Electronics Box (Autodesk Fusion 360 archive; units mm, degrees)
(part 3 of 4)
sketch "Sketch39" plane through (-44.05, 0, 0) normal (-1, 0, 0) x axis (0, -1, 0)
  line L1 (119.3333, 23.3545) -> (140.5403, 36.2986)
  line L2 (116.9188, 37.6536) -> (116.9188, 24.7095)
  line L3 (139.7132, 39.2411) -> (118.5063, 39.2411)
  line L4 (133.8107, 47.0651) -> (122.3147, 51.6626)
  line L5 (116.125, 44.0036) -> (133.2212, 44.0036)
  line L6 (114.5375, 47.3251) -> (114.5375, 45.5911)
  line L7 (153.8331, 21.6063) -> (153.8331, 36.0038)
  line L8 (128.6574, 20.0188) -> (152.2456, 20.0188)
  line L9 (151.4185, 37.3588) -> (127.8303, 22.9613)
  line L10 (87.9482, 38.7249) -> (109.672, 23.8539)
  line L11 (110.5688, 41.6224) -> (88.845, 41.6224)
  line L12 (112.1563, 25.1639) -> (112.1563, 40.0349)
  line L13 (136.171, 12.1797) -> (145.909, 8.5803)
  line L14 (152.2456, 15.2563) -> (136.7214, 15.2563)
  line L15 (153.8331, 13.1249) -> (153.8331, 13.6688)
  line L16 (106.0893, 20.535) -> (84.3655, 35.406)
  line L17 (83.4688, 17.6375) -> (105.1925, 17.6375)
  line L18 (81.8812, 34.096) -> (81.8813, 19.225)
  line L19 (143.8207, 57.3375) -> (129.195, 57.3375)
  line L20 (153.8331, 46.5316) -> (153.8331, 47.3251)
  line L21 (128.6056, 54.276) -> (151.6561, 45.0576)
  line L22 (124.5499, 3.1125) -> (138.0913, 3.1125)
  line L23 (138.6417, 6.189) -> (116.6477, 14.3188)
  line L24 (20.9087, 3.1125) -> (34.4501, 3.1125)
  line L25 (42.3523, 14.3188) -> (20.3583, 6.189)
  line L26 (29.805, 57.3375) -> (15.1793, 57.3375)
  line L27 (7.3439, 45.0576) -> (30.3944, 54.276)
  line L28 (5.1669, 47.3251) -> (5.1669, 46.5316)
  line L29 (74.6345, 35.406) -> (52.9107, 20.535)
  line L30 (77.1188, 19.225) -> (77.1188, 34.096)
  line L31 (53.8075, 17.6375) -> (75.5312, 17.6375)
  line L32 (34.5367, -1.65) -> (15.0927, -1.65)
  line L33 (104.6117, -1.65) -> (54.3883, -1.65)
  line L34 (143.9073, -1.65) -> (124.4633, -1.65)
  line L35 (158.5956, 47.4117) -> (158.5956, 13.0383)
  line L36 (124.4633, 62.1) -> (143.9073, 62.1)
  line L37 (54.3883, 62.1) -> (104.6117, 62.1)
  line L38 (15.0927, 62.1) -> (34.5367, 62.1)
  line L39 (0.4044, 13.0383) -> (0.4044, 47.4117)
  line L40 (5.1669, 13.6688) -> (5.1669, 13.1249)
  line L41 (22.2786, 15.2563) -> (6.7544, 15.2563)
  line L42 (13.091, 8.5803) -> (22.829, 12.1797)
  line L43 (46.8437, 40.0349) -> (46.8437, 25.1639)
  line L44 (70.155, 41.6224) -> (48.4312, 41.6224)
  line L45 (49.328, 23.8539) -> (71.0518, 38.7249)
  line L46 (5.1669, 36.0038) -> (5.1669, 21.6063)
  line L47 (31.1697, 22.9613) -> (7.5815, 37.3588)
  line L48 (6.7544, 20.0188) -> (30.3426, 20.0188)
  line L49 (44.4625, 45.5911) -> (44.4625, 47.3251)
  line L50 (25.7788, 44.0036) -> (42.875, 44.0036)
  line L51 (36.6853, 51.6626) -> (25.1893, 47.0651)
  line L52 (18.4597, 36.2986) -> (39.6667, 23.3545)
  line L53 (40.4937, 39.2411) -> (19.2868, 39.2411)
  line L54 (42.0812, 24.7095) -> (42.0812, 37.6536)
  line L55 (136.6611, 46) -> (156.8611, 46)
  line L56 (136.6611, 62.1) -> (136.6611, 46)
  line L57 (156.8611, 46) -> (156.8611, 62.1)
  line L58 (136.6611, 62.1) -> (156.8611, 62.1)
  line L59 (169.3015, 46) -> (136.6611, 46)
  line L60 (169.3015, 68.2941) -> (169.3015, 46)
  line L61 (136.6611, 68.2941) -> (169.3015, 68.2941)
  line L62 (136.6611, 46) -> (136.6611, 68.2941)
  line L63 (153.8331, 3.1125) -> (153.8331, 57.3375)
  circle C1 centre (108.075, 48.0849) radius 1.7
  circle C2 centre (89.025, 48.0849) radius 1.7
  arc A1 centre (118.5063, 24.7095) radius 1.5875 clockwise from (119.3333, 23.3545) to (116.9188, 24.7095)
  arc A2 centre (118.5063, 37.6536) radius 1.5875 clockwise from (116.9188, 37.6536) to (118.5063, 39.2411)
  arc A3 centre (139.7132, 37.6536) radius 1.5875 clockwise from (139.7132, 39.2411) to (140.5403, 36.2986)
  arc A4 centre (114.5375, 57.3375) radius 8.55 clockwise from (120.5996, 51.3081) to (115.8764, 48.893)
  arc A5 centre (121.7252, 50.1886) radius 1.5875 clockwise from (120.5996, 51.3081) to (122.3147, 51.6626)
  arc A6 centre (133.2212, 45.5911) radius 1.5875 clockwise from (133.8107, 47.0651) to (133.2212, 44.0036)
  arc A7 centre (116.125, 45.5911) radius 1.5875 clockwise from (116.125, 44.0036) to (114.5375, 45.5911)
  arc A8 centre (116.125, 47.3251) radius 1.5875 clockwise from (114.5375, 47.3251) to (115.8764, 48.893)
  arc A9 centre (152.2456, 21.6063) radius 1.5875 clockwise from (153.8331, 21.6063) to (152.2456, 20.0188)
  arc A10 centre (128.6574, 21.6063) radius 1.5875 clockwise from (128.6574, 20.0188) to (127.8303, 22.9613)
  arc A11 centre (152.2456, 36.0038) radius 1.5875 clockwise from (151.4185, 37.3588) to (153.8331, 36.0038)
  arc A12 centre (110.5688, 25.1639) radius 1.5875 clockwise from (112.1563, 25.1639) to (109.672, 23.8539)
  arc A13 centre (88.845, 40.0349) radius 1.5875 clockwise from (87.9482, 38.7249) to (88.845, 41.6224)
  arc A14 centre (110.5688, 40.0349) radius 1.5875 clockwise from (110.5688, 41.6224) to (112.1563, 40.0349)
  circle C3 centre (108.075, 11.175) radius 1.7
  circle C4 centre (89.025, 11.175) radius 1.7
  arc A15 centre (153.8331, 3.1125) radius 8.55 clockwise from (147.6141, 8.9799) to (152.4942, 11.557)
  arc A16 centre (146.4594, 10.0693) radius 1.5875 clockwise from (147.6141, 8.9799) to (145.909, 8.5803)
  arc A17 centre (136.7214, 13.6688) radius 1.5875 clockwise from (136.171, 12.1797) to (136.7214, 15.2563)
  arc A18 centre (152.2456, 13.6688) radius 1.5875 clockwise from (152.2456, 15.2563) to (153.8331, 13.6688)
  arc A19 centre (152.2456, 13.1249) radius 1.5875 clockwise from (153.8331, 13.1249) to (152.4942, 11.557)
  arc A20 centre (105.1925, 19.225) radius 1.5875 clockwise from (106.0893, 20.535) to (105.1925, 17.6375)
  arc A21 centre (83.4688, 19.225) radius 1.5875 clockwise from (83.4688, 17.6375) to (81.8813, 19.225)
  arc A22 centre (83.4687, 34.096) radius 1.5875 clockwise from (81.8812, 34.096) to (84.3655, 35.406)
  arc A23 centre (143.8207, 55.75) radius 1.5875 clockwise from (143.8207, 57.3375) to (145.3886, 55.9986)
  arc A24 centre (153.8331, 57.3375) radius 8.55 clockwise from (152.4942, 48.893) to (145.3886, 55.9986)
  arc A25 centre (152.2456, 47.3251) radius 1.5875 clockwise from (152.4942, 48.893) to (153.8331, 47.3251)
  arc A26 centre (152.2456, 46.5316) radius 1.5875 clockwise from (153.8331, 46.5316) to (151.6561, 45.0576)
  arc A27 centre (129.195, 55.75) radius 1.5875 clockwise from (128.6056, 54.276) to (129.195, 57.3375)
  arc A28 centre (124.5499, 4.7) radius 1.5875 clockwise from (124.5499, 3.1125) to (122.982, 4.4514)
  arc A29 centre (114.5375, 3.1125) radius 8.55 clockwise from (115.8764, 11.557) to (122.982, 4.4514)
  arc A30 centre (116.125, 13.1249) radius 1.5875 clockwise from (115.8764, 11.557) to (114.5375, 13.1249)
  arc A31 centre (116.0973, 12.8297) radius 1.5875 clockwise from (114.5375, 13.1249) to (116.6477, 14.3188)
  arc A32 centre (138.0913, 4.7) radius 1.5875 clockwise from (138.6417, 6.189) to (138.0913, 3.1125)
  circle C5 centre (114.5375, 3.1125) radius 2.2
  circle C6 centre (153.8331, 57.3375) radius 2.2
  circle C7 centre (114.5375, 57.3375) radius 2.2
  circle C8 centre (153.8331, 3.1125) radius 2.2
  circle C9 centre (5.1669, 3.1125) radius 2.2
  circle C10 centre (44.4625, 57.3375) radius 2.2
  circle C11 centre (5.1669, 57.3375) radius 2.2
  circle C12 centre (44.4625, 3.1125) radius 2.2
  arc A33 centre (20.9087, 4.7) radius 1.5875 clockwise from (20.9087, 3.1125) to (20.3583, 6.189)
  arc A34 centre (42.9027, 12.8297) radius 1.5875 clockwise from (42.3523, 14.3188) to (44.4625, 13.1249)
  arc A35 centre (42.875, 13.1249) radius 1.5875 clockwise from (44.4625, 13.1249) to (43.1236, 11.557)
  arc A36 centre (44.4625, 3.1125) radius 8.55 clockwise from (36.018, 4.4514) to (43.1236, 11.557)
  arc A37 centre (34.4501, 4.7) radius 1.5875 clockwise from (36.018, 4.4514) to (34.4501, 3.1125)
  arc A38 centre (29.805, 55.75) radius 1.5875 clockwise from (29.805, 57.3375) to (30.3944, 54.276)
  arc A39 centre (6.7544, 46.5316) radius 1.5875 clockwise from (7.3439, 45.0576) to (5.1669, 46.5316)
  arc A40 centre (6.7544, 47.3251) radius 1.5875 clockwise from (5.1669, 47.3251) to (6.5058, 48.893)
  arc A41 centre (5.1669, 57.3375) radius 8.55 clockwise from (13.6114, 55.9986) to (6.5058, 48.893)
  arc A42 centre (15.1793, 55.75) radius 1.5875 clockwise from (13.6114, 55.9986) to (15.1793, 57.3375)
  arc A43 centre (75.5312, 34.096) radius 1.5875 clockwise from (74.6345, 35.406) to (77.1188, 34.096)
  arc A44 centre (75.5312, 19.225) radius 1.5875 clockwise from (77.1188, 19.225) to (75.5312, 17.6375)
  arc A45 centre (53.8075, 19.225) radius 1.5875 clockwise from (53.8075, 17.6375) to (52.9107, 20.535)
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  point P233 (136.6611, 46)
  point P236 (136.6611, 46)
  point P73 (153.8331, 57.3375)
  point P240 (153.8331, 57.3375)
  point P48 (153.8331, 3.1125)
  point P241 (153.8331, 3.1125)
  point P242 (153.8331, 37.45)
  horizontal L59
  vertical L60
  horizontal L61
  vertical L62
  coincident P233 P236
  coincident P73 P240
  coincident P48 P241
  coincident L63 P242
  dimension "d441" diameter = 4.4 (= "threadedinsertdiam")
  dimension "d442" = 6.35
extrude "Extrude16" cut sketch "Sketch39" against normal blind 20.32
delete_face "DeleteFace6"
delete_face "DeleteFace7"
delete_face "DeleteFace8"
delete_face "DeleteFace9"
extrude "Extrude17" add sketch "Sketch39" against normal blind 6.35
delete_face "DeleteFace10"
fillet "Fillet6" radius 1.5875 (= "( 1 / 16 ) * 1 in")
fillet "Fillet7" radius 6.35
hole "Hole2" HoleDepth 10.0076 HoleDiameter 4.4 (= "threadedinsertdiam") TipAngle 180
move_face "MoveFace3"
sketch "Sketch40" plane through (0, 0, 74.8) normal (0, 0, 1) x axis (-1, 0, 0)
  line L1 (-98.3649, 123.85) -> (-98.3649, 92.3)
  line L2 (-75.3149, 123.85) -> (-98.3649, 123.85)
  line L3 (-75.3149, 92.3) -> (-75.3149, 123.85)
  line L4 (-98.3649, 92.3) -> (-75.3149, 92.3)
  line L5 (-118.7303, 25.9568) -> (-118.7303, 131.375)
  line L6 (33.9803, 25.9568) -> (-118.7303, 25.9568)
  line L7 (33.9803, 131.375) -> (33.9803, 25.9568)
  line L8 (-118.7303, 131.375) -> (33.9803, 131.375)
  line L9 (-76.5649, 35.4818) -> (-76.5649, 65.025)
  line L10 (-97.1149, 35.4818) -> (-76.5649, 35.4818)
  line L11 (-97.1149, 65.025) -> (-97.1149, 35.4818)
  line L12 (-76.5649, 65.025) -> (-97.1149, 65.025)
  line L13 (-107.4375, 25.9568) -> (-118.7303, 25.9568)
  line L14 (-118.7303, 131.375) -> (-107.4375, 131.375)
  line L15 (-118.7303, 25.9568) -> (-118.7303, 131.375)
  line L16 (22.6875, 25.9568) -> (33.9803, 25.9568)
  line L17 (22.6875, 131.375) -> (22.6875, 25.9568)
  line L18 (33.9803, 131.375) -> (22.6875, 131.375)
  line L19 (33.9803, 25.9568) -> (33.9803, 131.375)
  line L20 (-70.5524, 131.375) -> (-70.5524, 25.9568)
  line L21 (22.6875, 126.6125) -> (-70.5524, 126.6125)
  line L22 (22.6875, 30.7193) -> (-70.5524, 30.7193)
  line L23 (-47.2424, 126.6125) -> (-47.2424, 30.7193)
  line L24 (-23.9325, 30.7193) -> (-23.9325, 126.6125)
  line L25 (-0.6225, 126.6125) -> (-0.6225, 30.7193)
  line L26 (-70.5524, 54.6926) -> (-47.2424, 30.7193)
  line L27 (-47.2424, 78.6659) -> (-70.5524, 54.6926)
  line L28 (-70.5524, 102.6392) -> (-47.2424, 78.6659)
  line L29 (-47.2424, 126.6125) -> (-70.5524, 102.6392)
  line L30 (-47.2424, 54.6926) -> (-70.5524, 54.6926)
  line L31 (-47.2424, 102.6392) -> (-70.5524, 102.6392)
  line L32 (-70.5524, 78.6659) -> (-47.2424, 78.6659)
  line L33 (-23.9325, 54.6926) -> (-47.2424, 30.7193)
  line L34 (-47.2424, 78.6659) -> (-23.9325, 54.6926)
  line L35 (-47.2424, 54.6926) -> (-23.9325, 54.6926)
  line L36 (-23.9325, 78.6659) -> (-47.2424, 78.6659)
  line L37 (-23.9325, 102.6392) -> (-47.2424, 78.6659)
  line L38 (-23.9325, 102.6392) -> (-47.2424, 126.6125)
  line L39 (-47.2424, 102.6392) -> (-23.9325, 102.6392)
  line L40 (-0.6225, 78.6659) -> (-23.9325, 54.6926)
  line L41 (-0.6225, 54.6926) -> (-23.9325, 54.6926)
  line L42 (-23.9325, 54.6926) -> (-0.6225, 30.7193)
  line L43 (22.6875, 54.6926) -> (-0.6225, 30.7193)
  line L44 (-0.6225, 54.6926) -> (22.6875, 54.6926)
  line L45 (-0.6225, 78.6659) -> (22.6875, 54.6926)
  line L46 (22.6875, 102.6392) -> (-0.6225, 78.6659)
  line L47 (-0.6225, 126.6125) -> (22.6875, 102.6392)
  line L48 (-23.9325, 102.6392) -> (-0.6225, 126.6125)
  line L49 (-23.9325, 102.6392) -> (-0.6225, 78.6659)
  line L50 (-0.6225, 102.6392) -> (22.6875, 102.6392)
  line L51 (-0.6225, 102.6392) -> (-23.9325, 102.6392)
  line L52 (-23.9325, 78.6659) -> (-0.6225, 78.6659)
  line L53 (22.6875, 78.6659) -> (-0.6225, 78.6659)
  circle C1 centre (29.15, 51.2) radius 1.7
  circle C2 centre (29.15, 107.8) radius 1.7
  circle C3 centre (-113.9, 107.8) radius 1.7
  circle C4 centre (-113.9, 51.2) radius 1.7
  point P20 (-107.4375, 131.375)
  point P7 (-118.7303, 25.9568)
  point P18 (-118.7303, 25.9568)
  point P24 (22.6875, 131.375)
  point P8 (33.9803, 25.9568)
  point P22 (33.9803, 25.9568)
  point P26 (-70.5524, 25.9568)
  point P27 (-70.5524, 131.375)
  point P28 (-70.5524, 126.6125)
  point P29 (22.6875, 126.6125)
  point P30 (-70.5524, 30.7193)
  point P31 (22.6875, 30.7193)
  point P32 (-47.2424, 30.7193)
  point P33 (-47.2424, 126.6125)
  point P34 (-23.9325, 126.6125)
  point P35 (-23.9325, 30.7193)
  point P36 (-0.6225, 30.7193)
  point P37 (-0.6225, 126.6125)
  point P38 (-70.5524, 54.6926)
  point P39 (-47.2424, 78.6659)
  point P40 (-70.5524, 102.6392)
  point P41 (-47.2424, 54.6926)
  point P42 (-47.2424, 102.6392)
  point P43 (-70.5524, 78.6659)
  point P44 (-23.9325, 54.6926)
  point P45 (-47.2424, 54.6926)
  point P46 (-23.9325, 78.6659)
  point P47 (-23.9325, 102.6392)
  point P48 (-47.2424, 102.6392)
  point P52 (-0.6225, 30.7193)
  point P56 (-0.6225, 126.6125)
  point P53 (22.6875, 54.6926)
  point P50 (-0.6225, 78.6659)
  point P55 (22.6875, 102.6392)
  point P54 (-0.6225, 54.6926)
  point P58 (-0.6225, 102.6392)
  point P49 (-23.9325, 54.6926)
  point P51 (-0.6225, 54.6926)
  point P57 (-23.9325, 102.6392)
  point P59 (-0.6225, 102.6392)
  point P60 (-0.6225, 78.6659)
  point P61 (-23.9325, 78.6659)
  point P62 (-0.6225, 78.6659)
  point P63 (22.6875, 78.6659)
  point P15 (29.15, 107.8)
  point P5 (-75.3149, 92.3)
  horizontal L13
  horizontal L14
  vertical L15
  coincident L8 P20
  coincident P7 P18
  horizontal L16
  vertical L17
  horizontal L18
  vertical L19
  coincident L8 P24
  coincident P8 P22
  coincident L6 P26
  coincident L8 P27
  perpendicular L8 L20
  coincident L20 P28
  coincident L17 P29
  perpendicular L17 L21
  coincident L20 P30
  coincident L17 P31
  perpendicular L17 L22
  coincident L22 P32
  coincident L21 P33
  perpendicular L21 L23
  coincident L21 P34
  coincident L22 P35
  perpendicular L22 L24
  coincident L22 P36
  coincident L21 P37
  perpendicular L21 L25
  coincident L20 P38
  coincident L23 P39
  coincident L20 P40
  coincident L23 P41
  perpendicular L23 L30
  coincident L23 P42
  perpendicular L23 L31
  coincident L20 P43
  perpendicular L20 L32
  coincident L24 P44
  coincident L23 P45
  perpendicular L23 L35
  midpoint L24 P46
  coincident L24 P47
  coincident L23 P48
  perpendicular L23 L39
  symmetric P32 L24 P52
  symmetric P33 L24 P56
  symmetric L24 P38 P53
  symmetric L24 P39 P50
  symmetric L24 P40 P55
  symmetric L24 P41 P54
  symmetric L24 P42 P58
  symmetric L24 P44 P49
  symmetric L24 P45 P51
  symmetric L24 P47 P57
  symmetric L24 P48 P59
  symmetric L24 P39 P60
  symmetric L24 P46 P61
  symmetric L24 P39 P62
  symmetric L24 P43 P63
  dimension "d455" distance P15 L17 = 6.4625 (= "( ( 3 / 16 ) * 1 in ) + ( m3screwdiam / 2 )")
  dimension "d456" distance P5 L20 = 4.7625 (= "( 3 / 16 ) * 1 in")
  dimension "d457" distance L6 L22 = 4.7625 (= "( 3 / 16 ) * 1 in")
  dimension "d458" distance L8 L21 = 4.7625 (= "( 3 / 16 ) * 1 in")
  dimension "d459" distance L20 L23 = 23.31 (= "3.6708627805633998 in / 4")
  dimension "d460" distance L20 L24 = 46.62 (= "3.6708627805633998 in / 2")
  dimension "d461" distance L20 L25 = 69.9299 (= "3.6708627805633998 in * 0.75")
  dimension "d462" distance P33 P39 = 47.9466 (= "3.7753228345999998 in / 2")
  dimension "d463" distance P30 P38 = 23.9733 (= "3.7753228345999998 in / 4")
  dimension "d464" distance P35 P44 = 23.9733 (= "3.7753228345999998 in / 4")
  dimension "d465" distance P28 P40 = 23.9733 (= "3.7753228345999998 in / 4")
  dimension "d466" distance P34 P47 = 23.9733 (= "3.7753228345999998 in / 4")
hole "Hole1" HoleDepth 10.0076 HoleDiameter 3.4 (= "m3screwdiam") TipAngle 180
extrude "Extrude2" cut sketch "Sketch40" profile of L17 L20 L21 L22 L23 L24 L25 L26 L27 L28 L29 L30 L31 L32 L33 L34 L35 L36 L37 L38 L39 L40 L41 L42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 against normal blind 30.48
web "Web1" Thickness 4.7625 (= "( 3 / 16 ) * 1 in") Depth 6.35
fillet "Fillet1" radius 1.5875 (= "( 1 / 16 ) * 1 in")
hole "Hole2" HoleDepth 10.0076 HoleDiameter 4.4 (= "threadedinsertdiam") TipAngle 180
offset_faces "OffsetFaces1" distance -0.5
offset_faces "OffsetFaces2" distance 0.5
position "Position26"
sketch "Sketch41" plane through (0, 0, 68.45) normal (0, 0, 1) x axis (-1, 0, 0)
  line L1 (-90.9149, 154.35) -> (-90.9149, 141.35)
  line L2 (-88.4149, 157.35) -> (-90.9149, 154.35)
  line L3 (-85.2649, 157.35) -> (-88.4149, 157.35)
  line L4 (-82.7649, 154.35) -> (-85.2649, 157.35)
  line L5 (-82.7649, 141.35) -> (-82.7649, 154.35)
  line L6 (-90.9149, 141.35) -> (-82.7649, 141.35)
  line L7 (-93.1899, 97.475) -> (-80.4899, 97.475)
  line L8 (-93.1899, 118.675) -> (-93.1899, 97.475)
  line L9 (-80.4899, 118.675) -> (-93.1899, 118.675)
  line L10 (-80.4899, 97.475) -> (-80.4899, 118.675)
  line L11 (-116.1, 79.5) -> (-116.1, 158.6)
  line L12 (31.35, 79.5) -> (-116.1, 79.5)
  line L13 (31.35, 158.6) -> (31.35, 79.5)
  line L14 (-84.35, 190.35) -> (-0.4, 190.35)
  circle C1 centre (-113.9, 107.8) radius 1.7
  circle C2 centre (20.495, 179.495) radius 1.7
  circle C3 centre (-105.245, 179.495) radius 1.7
  circle C4 centre (29.15, 107.8) radius 1.7
  arc A1 centre (-0.4, 158.6) radius 31.75 clockwise from (-0.4, 190.35) to (31.35, 158.6)
  arc A2 centre (-84.35, 158.6) radius 31.75 clockwise from (-116.1, 158.6) to (-84.35, 190.35)
  circle C5 centre (-140.4555, 194.1596) radius 1.7
  circle C6 centre (-140.4555, 194.1596) radius 4.875
  dimension "d481" diameter C5 = 3.4 (= "m3screwdiam")
  dimension "d482" = 3.175
extrude "Extrude61" new body sketch "Sketch41" profile of C5 C6 along normal blind 6.35
move "Move2"
align "Align20"
copy_paste_bodies "CopyPasteBodies21"
move "Move23"
copy_paste_bodies "CopyPasteBodies22"
move "Move24"
copy_paste_bodies "CopyPasteBodies23"
move "Move25"
align "Align21"
align "Align22"
align "Align23"
component_from_bodies "Body->Comp9"
copy_paste_bodies "CutPasteBodies1"
copy_paste_bodies "CopyPasteBodies1"
move "Move2"
align "Align1"
copy_paste_bodies "CopyPasteBodies24"
move "Move26"
copy_paste_bodies "CopyPasteBodies25"
move "Move27"
copy_paste_bodies "CopyPasteBodies26"
move "Move28"
copy_paste_bodies "CopyPasteBodies27"
move "Move29"
copy_paste_bodies "CopyPasteBodies28"
move "Move30"
copy_paste_bodies "CopyPasteBodies29"
move "Move31"
copy_paste_bodies "CopyPasteBodies30"
move "Move32"
align "Align24"
align "Align25"
align "Align26"
align "Align27"
align "Align28"
align "Align29"
align "Align30"
mirror "Mirror10" mirrorStitchTolerance 0.1016
align "Align31"
copy_paste_bodies "CopyPasteBodies31"
move "Move33"
align "Align32"
copy_paste_bodies "CutPasteBodies2"
copy_paste "CutPaste8"
copy_paste_bodies "CopyPasteBodies32"
move "Move34"
align "Align33"
copy_paste_bodies "CopyPasteBodies33"
move "Move35"
align "Align34"
copy_paste_bodies "CopyPasteBodies34"
move "Move36"
align "Align35"
copy_paste_bodies "CopyPasteBodies35"
move "Move37"
align "Align36"
copy_paste_bodies "CutPasteBodies3"
copy_paste_bodies "CutPasteBodies5"
as_built_joint "As-built2"
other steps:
base_feature "Base Feature1"
base_feature "Base Feature1"
base_feature "Base Feature1"
base_feature "Base Feature1"
base_feature "Base Feature1"
base_feature "Base Feature1"
base_feature "Base Feature1"
base_feature "Base Feature1"
base_feature "Base Feature1"
base_feature "Base Feature1"
base_feature "Base Feature1"
base_feature "Base Feature2"
base_feature "Base Feature2"
base_feature "Base Feature2"
base_feature "Base Feature2"
base_feature "Base Feature2"
base_feature "Base Feature2"
base_feature "Base Feature2"
base_feature "Base Feature2"
base_feature "Base Feature2"
base_feature "Base Feature2"
base_feature "Base Feature3"
base_feature "Base Feature1"
base_feature "Base Feature4"
base_feature "Base Feature5"
base_feature "Base Feature2"
base_feature "Base Feature1"
delete_face "DeleteFace2"
delete_face "DeleteFace3"
delete_face "DeleteFace4"
base_feature "Base Feature6"
base_feature "Base Feature1"
base_feature "Base Feature2"
base_feature "Base Feature3"
base_feature "Base Feature3"
base_feature "Base Feature4"
base_feature "Base Feature1"
base_feature "Base Feature2"
base_feature "Base Feature3"
base_feature "Base Feature4"
base_feature "Base Feature5"
base_feature "Base Feature6"
base_feature "Base Feature7"
base_feature "Base Feature8"
base_feature "Base Feature9"
base_feature "Base Feature10"
base_feature "Base Feature11"
base_feature "Base Feature12"
base_feature "Base Feature13"
base_feature "Base Feature14"
base_feature "Base Feature15"
base_feature "Base Feature16"
base_feature "Base Feature17"
base_feature "Base Feature18"
base_feature "Base Feature19"
base_feature "Base Feature20"
base_feature "Base Feature21"
base_feature "Base Feature22"
base_feature "Base Feature23"
base_feature "Base Feature24"
base_feature "Base Feature25"
base_feature "Base Feature26"
base_feature "Base Feature27"
base_feature "Base Feature28"
base_feature "Base Feature29"
base_feature "Base Feature30"
base_feature "Base Feature31"
base_feature "Base Feature32"
base_feature "Base Feature33"
base_feature "Base Feature34"
base_feature "Base Feature35"
create_component "CreateComponent1"
remove_instance "RemoveInstance1"
remove_instance "RemoveInstance2"
remove_instance "RemoveInstance3"
remove_instance "RemoveInstance4"
remove_instance "RemoveInstance5"
remove_instance "RemoveInstance6"
remove_instance "RemoveInstance7"
remove_instance "RemoveInstance8"
create_component "CreateComponent2"
remove_instance "RemoveInstance9"
remove_instance "RemoveInstance10"
remove_instance "RemoveInstance11"
create_component "CreateComponent3"
remove_instance "RemoveInstance12"
remove_instance "RemoveInstance13"
remove_instance "RemoveInstance14"
remove_instance "RemoveInstance15"
create_component "CreateComponent4"
remove_body "RemoveBody3"
remove_body "RemoveBody4"
create_component "CreateComponent5"
remove_body "RemoveBody5"
create_component "CreateComponent6"
remove_body "RemoveBody6"
remove_body "RemoveBody7"
remove_body "RemoveBody8"
create_component "CreateComponent7"
remove_body "RemoveBody9"
remove_body "RemoveBody10"
create_component "CreateComponent8"
create_component "CreateComponent9"
remove_instance "RemoveInstance16"
remove_instance "RemoveInstance17"
remove_instance "RemoveInstance18"
remove_instance "RemoveInstance19"
remove_instance "RemoveInstance20"
create_component "CreateComponent10"
create_component "CreateComponent1"
remove_body "RemoveBody1"
create_component "CreateComponent2"
remove_body "RemoveBody2"
remove_body "RemoveBody11"
remove_body "RemoveBody12"
remove_body "RemoveBody13"
remove_body "RemoveBody14"
remove_body "RemoveBody15"
remove_body "RemoveBody16"
remove_body "RemoveBody17"
remove_body "RemoveBody18"
remove_body "RemoveBody19"
remove_body "RemoveBody20"
remove_body "RemoveBody21"
remove_body "RemoveBody22"
remove_body "RemoveBody23"
remove_body "RemoveBody24"
remove_instance "RemoveInstance21"
create_component "CreateComponent1"
create_component "CreateComponent2"
create_component "CreateComponent11"
remove_body "RemoveBody25"
remove_body "RemoveBody26"
remove_body "RemoveBody27"
remove_body "RemoveBody28"
remove_body "RemoveBody29"
remove_instance "RemoveInstance22"
create_component "CreateComponent12"
remove_body "RemoveBody30"
remove_instance "RemoveInstance23"
create_component "CreateComponent1"
remove_body "RemoveBody1"
remove_body "RemoveBody2"
remove_instance "RemoveInstance1"
create_component "CreateComponent13"
remove_body "RemoveBody31"
remove_instance "RemoveInstance24"
remove_body "RemoveBody32"
remove_body "RemoveBody33"
remove_body "RemoveBody34"
create_component "CreateComponent14"
remove_body "RemoveBody35"
remove_instance "RemoveInstance25"
remove_body "RemoveBody36"
create_component "CreateComponent15"
remove_body "RemoveBody37"
remove_instance "RemoveInstance26"
remove_body "RemoveBody1"
remove_body "RemoveBody38"
remove_body "RemoveBody39"
create_component "CreateComponent2"
remove_body "RemoveBody5"
remove_instance "RemoveInstance2"
remove_instance "RemoveInstance27"
remove_body "RemoveBody40"
create_component "CreateComponent16"
remove_body "RemoveBody41"
remove_body "RemoveBody42"
remove_body "RemoveBody43"
remove_body "RemoveBody44"
remove_body "RemoveBody45"
remove_body "RemoveBody46"
remove_body "RemoveBody47"
remove_body "RemoveBody48"
remove_body "RemoveBody49"
remove_body "RemoveBody50"
remove_body "RemoveBody51"
remove_body "RemoveBody52"
remove_body "RemoveBody53"
remove_body "RemoveBody54"
remove_body "RemoveBody55"
remove_body "RemoveBody56"
remove_body "RemoveBody57"
remove_body "RemoveBody58"
remove_body "RemoveBody59"
remove_instance "RemoveInstance28"
remove_body "RemoveBody60"
remove_body "RemoveBody61"
remove_body "RemoveBody62"
remove_body "RemoveBody63"
remove_body "RemoveBody3"
remove_body "RemoveBody4"
remove_body "RemoveBody5"
remove_body "RemoveBody6"
remove_body "RemoveBody7"
remove_body "RemoveBody8"
remove_body "RemoveBody9"
remove_body "RemoveBody10"
remove_body "RemoveBody11"
remove_body "RemoveBody12"
remove_body "RemoveBody13"
remove_body "RemoveBody14"
remove_body "RemoveBody15"
remove_body "RemoveBody16"
remove_body "RemoveBody17"
remove_body "RemoveBody18"
remove_body "RemoveBody19"
remove_body "RemoveBody20"
remove_body "RemoveBody21"
remove_body "RemoveBody22"

design "half proto board"
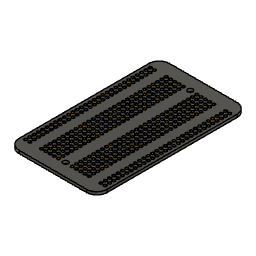
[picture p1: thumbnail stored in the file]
sketch "Sketch1" plane through (0, 0, 0) normal (0, 0, 1) x axis (1, 0, 0)
  line L1 (-26.05, -44.5) -> (26.05, -44.5)
  line L2 (-26.05, 44.5) -> (-26.05, -44.5)
  line L3 (26.05, 44.5) -> (-26.05, 44.5)
  line L4 (26.05, -44.5) -> (26.05, 44.5)
  line L5 (-26.05, 44.5) -> (26.05, -44.5)
  line L6 (26.05, 44.5) -> (-26.05, -44.5)
  line L7 (0, 44.5) -> (0, -44.5)
  line L8 (26.05, 0) -> (0, 0)
  line L9 (23.55, 44.5) -> (23.55, -44.5)
  line L10 (21.05, 44.5) -> (21.05, -44.5)
  line L11 (14.05, 44.5) -> (14.05, -44.5)
  circle C1 centre (0, -36.85) radius 1.5
  circle C2 centre (0, 36.85) radius 1.5
  circle C3 centre (23.55, -37) radius 0.65
  circle C4 centre (21.05, -37) radius 0.65
  circle C5 centre (21.05, -37) radius 0.85
  circle C6 centre (23.55, -37) radius 0.85
  circle C7 centre (14.05, -37) radius 0.65
  circle C8 centre (14.05, -37) radius 0.85
  point P6 (0, 0)
  point P1 (0, 0)
  point P7 (0, -44.5)
  point P8 (0, 44.5)
  point P9 (0, -36.85)
  point P10 (0, 0)
  point P11 (26.05, 0)
  point P13 (23.55, -44.5)
  point P14 (23.55, 44.5)
  point P15 (21.05, -44.5)
  point P16 (21.05, 44.5)
  point P17 (14.05, -44.5)
  point P18 (14.05, 44.5)
  point P19 (23.55, -37)
  point P20 (21.05, -37)
  point P23 (14.05, -37)
  point P2 (26.05, -44.5)
  point P5 (26.05, 44.5)
  horizontal L1
  perpendicular L1 L2
  parallel L1 L3
  parallel L2 L4
  coincident L5 P6
  coincident L6 P6
  coincident P1 P6
  midpoint L1 P7
  midpoint L3 P8
  coincident L7 P9
  coincident P1 P10
  midpoint L4 P11
  symmetric C1 L8 C2
  coincident L1 P13
  coincident L3 P14
  perpendicular L3 L9
  coincident L1 P15
  coincident L3 P16
  perpendicular L3 L10
  coincident L1 P17
  coincident L3 P18
  perpendicular L3 L11
  coincident L9 P19
  coincident L10 P20
  coincident L11 P23
  dimension "d1" distance P2 P5 = 89
  dimension "d2" distance L2 L4 = 52.1
  dimension "d3" diameter C1 = 3
  dimension "d4" distance P7 P9 = 7.65
  dimension "d9" distance L4 L9 = 2.5
  dimension "d10" distance L4 L10 = 5
  dimension "d11" distance L1 P20 = 7.5
  dimension "d12" distance L1 P19 = 7.5
  dimension "d13" diameter C3 = 1.3
  dimension "d14" diameter C4 = 1.3
  dimension "d15" = 0.2
  dimension "d16" = 0.2
  dimension "d17" distance L4 L11 = 12
  dimension "d18" diameter C7 = 1.3
  dimension "d19" = 0.2
  dimension "d20" distance L1 P23 = 7.5
extrude "Extrude1" new body sketch "Sketch1" profile of L1 L2 L3 L4 C1 C2 C3 C4 C5 C6 C7 C8 against normal blind 1.65
fillet "Fillet1" radius 6.1
extrude "Extrude2" cut sketch "Sketch1" profile of C3 C4 C5 C6 C7 C8 against normal blind 4
extrude "Extrude3" new body sketch "Sketch1" profile of C3 C4 C5 C6 C7 C8 against normal blind 1.65
rectangular_pattern "R-Pattern1" uSpaceDistance 2.5 vSpaceDistance 0
rectangular_pattern "R-Pattern2" uSpaceDistance -2.5 vSpaceDistance 0
copy_paste_bodies "CutPasteBodies1"
rectangular_pattern "R-Pattern3" countU 30 uSpaceDistance 73.7 vSpaceDistance 0
split "Split1"
remove_body "RemoveBody8"
mirror "Mirror1" mirrorStitchTolerance 0.1
rectangular_pattern "R-Pattern2" countU 30 uSpaceDistance -73.7 vSpaceDistance 0
mirror "Mirror1" mirrorStitchTolerance 0.1
component_from_bodies "Body->Comp1"
copy_paste "CutPaste"
component_from_bodies "Body->Comp1"
copy_paste_bodies "CutPasteBodies1"
as_built_joint "As-built1"
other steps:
base_feature "Base Feature1"
base_feature "Base Feature1"
base_feature "Base Feature1"
base_feature "Base Feature2"
create_component "CreateComponent1"
remove_body "RemoveBody1"
remove_body "RemoveBody2"
remove_body "RemoveBody3"
remove_body "RemoveBody4"
remove_body "RemoveBody5"
remove_body "RemoveBody6"
remove_body "RemoveBody7"
create_component "CreateComponent2"
remove_body "RemoveBody9"
remove_instance "RemoveInstance1"
create_component "CreateComponent1"
remove_body "RemoveBody1"
remove_body "RemoveBody2"
remove_body "RemoveBody3"
remove_body "RemoveBody4"
remove_body "RemoveBody5"
remove_body "RemoveBody6"
remove_body "RemoveBody7"
remove_body "RemoveBody8"
remove_body "RemoveBody9"
remove_body "RemoveBody10"
remove_body "RemoveBody11"
remove_body "RemoveBody12"
remove_body "RemoveBody13"
remove_body "RemoveBody14"
remove_body "RemoveBody15"
remove_body "RemoveBody16"
remove_body "RemoveBody17"
remove_body "RemoveBody18"
remove_body "RemoveBody19"
remove_body "RemoveBody20"
remove_body "RemoveBody21"
remove_body "RemoveBody22"
remove_body "RemoveBody23"
remove_body "RemoveBody24"
remove_body "RemoveBody25"
remove_body "RemoveBody26"
remove_body "RemoveBody27"
remove_body "RemoveBody28"
remove_body "RemoveBody29"
remove_body "RemoveBody30"
remove_body "RemoveBody31"
remove_body "RemoveBody32"
remove_body "RemoveBody33"
remove_body "RemoveBody34"
remove_body "RemoveBody35"
remove_body "RemoveBody36"
remove_body "RemoveBody37"
remove_body "RemoveBody38"
remove_body "RemoveBody39"
remove_body "RemoveBody40"
remove_body "RemoveBody41"
remove_body "RemoveBody42"
remove_body "RemoveBody43"
remove_body "RemoveBody44"
remove_body "RemoveBody45"
remove_body "RemoveBody46"
remove_body "RemoveBody47"
remove_body "RemoveBody48"
remove_body "RemoveBody49"
remove_body "RemoveBody50"
remove_body "RemoveBody51"
remove_body "RemoveBody52"
remove_body "RemoveBody53"
remove_body "RemoveBody54"
remove_body "RemoveBody55"
remove_body "RemoveBody56"
remove_body "RemoveBody57"
remove_body "RemoveBody58"
remove_body "RemoveBody59"
remove_body "RemoveBody60"
remove_body "RemoveBody61"
remove_body "RemoveBody62"
remove_body "RemoveBody63"
remove_body "RemoveBody64"
remove_body "RemoveBody65"
remove_body "RemoveBody66"
remove_body "RemoveBody67"
remove_body "RemoveBody68"
remove_body "RemoveBody69"
remove_body "RemoveBody70"
remove_body "RemoveBody71"
remove_body "RemoveBody72"
remove_body "RemoveBody73"
remove_body "RemoveBody74"
remove_body "RemoveBody75"
remove_body "RemoveBody76"
remove_body "RemoveBody77"
remove_body "RemoveBody78"
remove_body "RemoveBody79"
remove_body "RemoveBody80"
remove_body "RemoveBody81"
remove_body "RemoveBody82"
remove_body "RemoveBody83"
remove_body "RemoveBody84"
remove_body "RemoveBody85"
remove_body "RemoveBody86"
remove_body "RemoveBody87"
remove_body "RemoveBody88"
remove_body "RemoveBody89"
remove_body "RemoveBody90"
remove_body "RemoveBody91"
remove_body "RemoveBody92"
remove_body "RemoveBody93"
remove_body "RemoveBody94"
remove_body "RemoveBody95"
remove_body "RemoveBody96"
remove_body "RemoveBody97"
remove_body "RemoveBody98"
remove_body "RemoveBody99"
remove_body "RemoveBody100"
remove_body "RemoveBody101"
remove_body "RemoveBody102"
remove_body "RemoveBody103"
remove_body "RemoveBody104"
remove_body "RemoveBody105"
remove_body "RemoveBody106"
remove_body "RemoveBody107"
remove_body "RemoveBody108"
remove_body "RemoveBody109"
remove_body "RemoveBody110"
remove_body "RemoveBody111"
remove_body "RemoveBody112"
remove_body "RemoveBody113"
remove_body "RemoveBody114"
remove_body "RemoveBody115"
remove_body "RemoveBody116"
remove_body "RemoveBody117"
remove_body "RemoveBody118"
remove_body "RemoveBody119"
remove_body "RemoveBody120"
remove_body "RemoveBody121"
remove_body "RemoveBody122"
remove_body "RemoveBody123"
remove_body "RemoveBody124"
remove_body "RemoveBody125"
remove_body "RemoveBody126"
remove_body "RemoveBody127"
remove_body "RemoveBody128"
remove_body "RemoveBody129"
remove_body "RemoveBody130"
remove_body "RemoveBody131"
remove_body "RemoveBody132"
remove_body "RemoveBody133"
remove_body "RemoveBody134"
remove_body "RemoveBody135"
remove_body "RemoveBody136"
remove_body "RemoveBody137"
remove_body "RemoveBody138"
remove_body "RemoveBody139"
remove_body "RemoveBody140"
remove_body "RemoveBody141"
remove_body "RemoveBody142"
remove_body "RemoveBody143"
remove_body "RemoveBody144"
remove_body "RemoveBody145"
remove_body "RemoveBody146"
remove_body "RemoveBody147"
remove_body "RemoveBody148"
remove_body "RemoveBody149"
remove_body "RemoveBody150"
remove_body "RemoveBody151"
remove_body "RemoveBody152"
remove_body "RemoveBody153"
remove_body "RemoveBody154"
remove_body "RemoveBody155"
remove_body "RemoveBody156"
remove_body "RemoveBody157"
remove_body "RemoveBody158"
remove_body "RemoveBody159"
remove_body "RemoveBody160"
remove_body "RemoveBody161"
remove_body "RemoveBody162"
remove_body "RemoveBody163"
remove_body "RemoveBody164"
remove_body "RemoveBody165"
remove_body "RemoveBody166"
remove_body "RemoveBody167"
remove_body "RemoveBody168"
remove_body "RemoveBody169"
remove_body "RemoveBody170"
remove_body "RemoveBody171"
remove_body "RemoveBody172"
remove_body "RemoveBody173"
remove_body "RemoveBody174"
remove_body "RemoveBody175"
remove_body "RemoveBody176"
remove_body "RemoveBody177"
remove_body "RemoveBody178"
remove_body "RemoveBody179"
remove_body "RemoveBody180"
remove_body "RemoveBody181"
remove_body "RemoveBody182"
remove_body "RemoveBody183"
remove_body "RemoveBody184"
remove_body "RemoveBody185"
remove_body "RemoveBody186"
remove_body "RemoveBody187"
remove_body "RemoveBody188"
remove_body "RemoveBody189"
remove_body "RemoveBody190"
remove_body "RemoveBody191"
remove_body "RemoveBody192"
remove_body "RemoveBody193"
remove_body "RemoveBody194"
remove_body "RemoveBody195"
remove_body "RemoveBody196"
remove_body "RemoveBody197"
remove_body "RemoveBody198"
remove_body "RemoveBody199"
remove_body "RemoveBody200"
remove_body "RemoveBody201"
remove_body "RemoveBody202"
remove_body "RemoveBody203"
remove_body "RemoveBody204"
remove_body "RemoveBody205"
remove_body "RemoveBody206"
remove_body "RemoveBody207"
remove_body "RemoveBody208"
remove_body "RemoveBody209"
remove_body "RemoveBody210"
remove_body "RemoveBody211"
remove_body "RemoveBody212"
remove_body "RemoveBody213"
remove_body "RemoveBody214"
remove_body "RemoveBody215"
remove_body "RemoveBody216"
remove_body "RemoveBody217"
remove_body "RemoveBody218"
remove_body "RemoveBody219"
remove_body "RemoveBody220"
remove_body "RemoveBody221"
remove_body "RemoveBody222"
remove_body "RemoveBody223"
remove_body "RemoveBody224"
remove_body "RemoveBody225"
remove_body "RemoveBody226"
remove_body "RemoveBody227"
remove_body "RemoveBody228"
remove_body "RemoveBody229"
remove_body "RemoveBody230"
remove_body "RemoveBody231"
remove_body "RemoveBody232"
remove_body "RemoveBody233"
remove_body "RemoveBody234"
remove_body "RemoveBody235"
remove_body "RemoveBody236"
remove_body "RemoveBody237"
remove_body "RemoveBody238"
remove_body "RemoveBody239"
remove_body "RemoveBody240"
remove_body "RemoveBody241"
remove_body "RemoveBody242"
remove_body "RemoveBody243"
remove_body "RemoveBody244"
remove_body "RemoveBody245"
remove_body "RemoveBody246"
remove_body "RemoveBody247"
remove_body "RemoveBody248"
remove_body "RemoveBody249"
remove_body "RemoveBody250"
remove_body "RemoveBody251"
remove_body "RemoveBody252"
remove_body "RemoveBody253"
remove_body "RemoveBody254"
remove_body "RemoveBody255"
remove_body "RemoveBody256"
remove_body "RemoveBody257"
remove_body "RemoveBody258"
remove_body "RemoveBody259"
remove_body "RemoveBody260"
remove_body "RemoveBody261"
remove_body "RemoveBody262"
remove_body "RemoveBody263"
remove_body "RemoveBody264"
remove_body "RemoveBody265"
remove_body "RemoveBody266"
remove_body "RemoveBody267"
remove_body "RemoveBody268"
remove_body "RemoveBody269"
remove_body "RemoveBody270"
remove_body "RemoveBody271"
remove_body "RemoveBody272"
remove_body "RemoveBody273"
remove_body "RemoveBody274"
remove_body "RemoveBody275"
remove_body "RemoveBody276"
remove_body "RemoveBody277"
remove_body "RemoveBody278"
remove_body "RemoveBody279"
remove_body "RemoveBody280"
remove_body "RemoveBody281"
remove_body "RemoveBody282"
remove_body "RemoveBody283"
remove_body "RemoveBody284"
remove_body "RemoveBody285"
remove_body "RemoveBody286"
remove_body "RemoveBody287"
remove_body "RemoveBody288"
remove_body "RemoveBody289"
remove_body "RemoveBody290"
remove_body "RemoveBody291"
remove_body "RemoveBody292"
remove_body "RemoveBody293"
remove_body "RemoveBody294"
remove_body "RemoveBody295"
remove_body "RemoveBody296"
remove_body "RemoveBody297"
remove_body "RemoveBody298"
remove_body "RemoveBody299"
remove_body "RemoveBody300"
remove_body "RemoveBody301"
remove_body "RemoveBody302"
remove_body "RemoveBody303"
remove_body "RemoveBody304"
remove_body "RemoveBody305"
remove_body "RemoveBody306"
remove_body "RemoveBody307"
remove_body "RemoveBody308"
remove_body "RemoveBody309"
remove_body "RemoveBody310"
remove_body "RemoveBody311"
remove_body "RemoveBody312"
remove_body "RemoveBody313"
remove_body "RemoveBody314"
remove_body "RemoveBody315"
remove_body "RemoveBody316"
remove_body "RemoveBody317"
remove_body "RemoveBody318"
remove_body "RemoveBody319"
remove_body "RemoveBody320"
remove_body "RemoveBody321"
remove_body "RemoveBody322"
remove_body "RemoveBody323"
remove_body "RemoveBody324"
remove_body "RemoveBody325"
remove_body "RemoveBody326"
remove_body "RemoveBody327"
remove_body "RemoveBody328"
remove_body "RemoveBody329"
remove_body "RemoveBody330"
remove_body "RemoveBody331"
remove_body "RemoveBody332"
remove_body "RemoveBody333"
remove_body "RemoveBody334"
remove_body "RemoveBody335"
remove_body "RemoveBody336"
remove_body "RemoveBody337"
remove_body "RemoveBody338"
remove_body "RemoveBody339"
remove_body "RemoveBody340"
remove_body "RemoveBody341"
remove_body "RemoveBody342"
remove_body "RemoveBody343"
remove_body "RemoveBody344"
remove_body "RemoveBody345"
remove_body "RemoveBody346"
remove_body "RemoveBody347"
remove_body "RemoveBody348"
remove_body "RemoveBody349"
remove_body "RemoveBody350"
remove_body "RemoveBody351"
remove_body "RemoveBody352"
remove_body "RemoveBody353"
remove_body "RemoveBody354"
remove_body "RemoveBody355"
remove_body "RemoveBody356"
remove_body "RemoveBody357"
remove_body "RemoveBody358"
remove_body "RemoveBody359"
remove_body "RemoveBody360"
remove_body "RemoveBody361"
remove_body "RemoveBody362"
remove_body "RemoveBody363"
remove_body "RemoveBody364"
remove_body "RemoveBody365"
remove_body "RemoveBody366"
remove_body "RemoveBody367"
remove_body "RemoveBody368"
remove_body "RemoveBody369"
remove_body "RemoveBody370"
remove_body "RemoveBody371"
remove_body "RemoveBody372"
remove_body "RemoveBody373"
remove_body "RemoveBody374"
remove_body "RemoveBody375"
remove_body "RemoveBody376"
remove_body "RemoveBody377"
remove_body "RemoveBody378"
remove_body "RemoveBody379"
remove_body "RemoveBody380"
remove_body "RemoveBody381"
remove_body "RemoveBody382"
remove_body "RemoveBody383"
remove_body "RemoveBody384"
remove_body "RemoveBody385"
remove_body "RemoveBody386"
remove_body "RemoveBody387"
remove_body "RemoveBody388"
remove_body "RemoveBody389"
remove_body "RemoveBody390"
remove_body "RemoveBody391"
remove_body "RemoveBody392"
remove_body "RemoveBody393"
remove_body "RemoveBody394"
remove_body "RemoveBody395"
remove_body "RemoveBody396"
remove_body "RemoveBody397"
remove_body "RemoveBody398"
remove_body "RemoveBody399"
remove_body "RemoveBody400"
remove_body "RemoveBody401"
remove_body "RemoveBody402"
remove_body "RemoveBody403"
remove_body "RemoveBody404"
remove_body "RemoveBody405"
remove_body "RemoveBody406"
remove_body "RemoveBody407"
remove_body "RemoveBody408"
remove_body "RemoveBody409"
remove_body "RemoveBody410"
remove_body "RemoveBody411"
remove_body "RemoveBody412"
remove_body "RemoveBody413"
remove_body "RemoveBody414"
remove_body "RemoveBody415"
remove_body "RemoveBody416"
remove_body "RemoveBody417"
remove_body "RemoveBody418"
remove_body "RemoveBody419"
remove_body "RemoveBody420"

design "BTS790 Motor Driver"
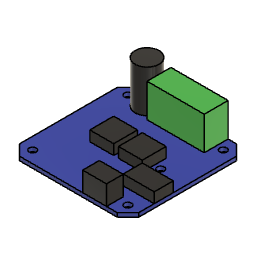
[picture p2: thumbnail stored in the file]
sketch "Sketch1" plane through (0, 0, 0) normal (0, 0, 1) x axis (1, 0, 0)
  line L1 (-25, -25) -> (25, -25)
  line L2 (-25, 25) -> (-25, -25)
  line L3 (25, 25) -> (-25, 25)
  line L4 (25, -25) -> (25, 25)
  line L5 (-25, 25) -> (25, -25)
  line L6 (25, 25) -> (-25, -25)
  line L7 (17, 25) -> (-7, 25)
  line L8 (17, 15) -> (17, 25)
  line L9 (-7, 15) -> (17, 15)
  line L10 (-7, 25) -> (-7, 15)
  line L11 (6, -25) -> (16, -25)
  line L12 (6, -18) -> (6, -25)
  line L13 (16, -18) -> (6, -18)
  line L14 (16, -25) -> (16, -18)
  line L15 (1, -5) -> (11, -5)
  line L16 (1, 5) -> (1, -5)
  line L17 (11, 5) -> (1, 5)
  line L18 (11, -5) -> (11, 5)
  line L19 (1, 5) -> (11, -5)
  line L20 (11, 5) -> (1, -5)
  line L21 (25, 0) -> (0, 0)
  line L22 (0, -25) -> (0, 0)
  line L23 (-11, 5) -> (-1, 5)
  line L24 (-11, -5) -> (-11, 5)
  line L25 (-1, 5) -> (-1, -5)
  line L26 (-1, -5) -> (-11, -5)
  line L27 (25, -6) -> (12, -6)
  line L28 (25, -14) -> (25, -6)
  line L29 (12, -14) -> (25, -14)
  line L30 (12, -6) -> (12, -14)
  line L31 (25, 0) -> (-25, 0)
  circle C1 centre (-12, 20) radius 5
  circle C2 centre (13.75, 0) radius 1.5
  circle C3 centre (-13.75, 0) radius 1.5
  circle C4 centre (-20, 20) radius 1.5
  circle C5 centre (-20, -20) radius 1.5
  point P6 (0, 0)
  point P1 (0, 0)
  point P7 (-7, 25)
  point P12 (16, -25)
  point P21 (6, 0)
  point P22 (0, 0)
  point P23 (25, 0)
  point P24 (0, 0)
  point P25 (0, -25)
  point P17 (11, -5)
  point P28 (-11, -5)
  point P18 (1, -5)
  point P29 (-1, -5)
  point P19 (1, 5)
  point P26 (-1, 5)
  point P20 (11, 5)
  point P27 (-11, 5)
  point P5 (25, 25)
  point P35 (-20, 20)
  point P16 (13.75, 0)
  point P36 (-20, -20)
  point P37 (-25, 0)
  point P4 (-25, 25)
  point P31 (12, -6)
  point P32 (25, -6)
  horizontal L1
  perpendicular L1 L2
  parallel L1 L3
  parallel L2 L4
  coincident L5 P6
  coincident L6 P6
  coincident P1 P6
  horizontal L7
  vertical L8
  horizontal L9
  vertical L10
  coincident L3 P7
  tangent L10 C1
  tangent L3 C1
  horizontal L11
  vertical L12
  horizontal L13
  vertical L14
  coincident L1 P12
  horizontal L15
  perpendicular L15 L16
  parallel L15 L17
  parallel L16 L18
  coincident L19 P21
  coincident L20 P21
  coincident P1 P22
  midpoint L4 P23
  coincident P21 L21
  coincident P6 P24
  midpoint L1 P25
  symmetric C2 L22 C3
  symmetric P17 L22 P28
  symmetric P18 L22 P29
  symmetric P19 L22 P26
  symmetric P20 L22 P27
  horizontal L27
  vertical L28
  horizontal L29
  vertical L30
  coincident P5 L28
  coincident L5 P35
  coincident P16 L21
  coincident L6 P36
  midpoint L2 P37
  symmetric C4 C5 L31
  dimension "d1" distance P4 P5 = 50
  dimension "d2" distance L1 L3 = 50
  dimension "d3" distance L4 L8 = 8
  dimension "d4" distance L2 L10 = 18
  dimension "d5" distance L3 L9 = 10
  dimension "d6" diameter C1 = 10
  dimension "d7" distance L4 L14 = 9
  dimension "d8" distance L12 L14 = 10
  dimension "d9" distance L1 L13 = 7
  dimension "d11" distance P1 P16 = 13.75 (= "( 27.5 / 2 ) * 1 mm")
  dimension "d12" diameter C2 = 3
  dimension "d13" distance P19 P20 = 10
  dimension "d14" distance P17 P20 = 10
  dimension "d15" distance P1 P21 = 6
  dimension "d17" distance P31 P32 = 13
  dimension "d18" distance L13 L29 = 4
  dimension "d19" distance L27 L29 = 8
  dimension "d33" diameter C4 = 3
  dimension "d34" distance P35 P36 = 40 (= "37 mm + 3 mm")
extrude "Extrude1" new body sketch "Sketch1" profile of L1 L2 L3 L4 L7 L8 L9 L10 C1 L11 L12 L13 L14 C2 L15 L16 L17 L18 L23 L24 L25 L26 C3 L27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 against normal blind 1.65
extrude "Extrude2" new body sketch "Sketch1" profile of C1 along normal blind 17.65
extrude "Extrude3" new body sketch "Sketch1" profile of L3 L7 L8 L9 L10 along normal blind 14
extrude "Extrude4" new body sketch "Sketch1" profile of L15 L16 L17 L18 L23 L24 L25 L26 along normal blind 4.3
extrude "Extrude5" new body sketch "Sketch1" profile of L4 L27 L28 L29 L30 along normal blind 4.3
extrude "Extrude6" new body sketch "Sketch1" profile of L1 L11 L12 L13 L14 along normal blind 8.2
chamfer "Chamfer1" distance 4.5
component_from_bodies "Body->Comp"
copy_paste_bodies "CutPasteBodies"
extrude "Extrude1" cut sketch "Sketch1" profile of C4 C5 against normal blind 17
mirror "Mirror1" mirrorStitchTolerance 0.1
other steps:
base_feature "Base Feature1"
base_feature "Base Feature2"
create_component "CreateComponent1"
remove_body "RemoveBody1"
remove_body "RemoveBody2"
remove_body "RemoveBody3"
remove_body "RemoveBody4"
remove_body "RemoveBody5"
remove_body "RemoveBody6"
remove_body "RemoveBody7"

design "USB host shield"
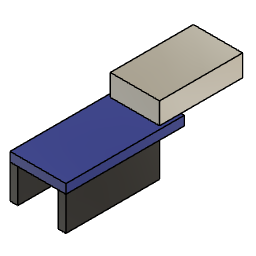
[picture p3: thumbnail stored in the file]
sketch "Sketch1" plane through (0, 0, 0) normal (0, 0, 1) x axis (1, 0, 0)
  line L1 (-9.075, -19.25) -> (9.075, -19.25)
  line L2 (-9.075, 19.25) -> (-9.075, -19.25)
  line L3 (9.075, 19.25) -> (-9.075, 19.25)
  line L4 (9.075, -19.25) -> (9.075, 19.25)
  line L5 (-9.075, 19.25) -> (9.075, -19.25)
  line L6 (9.075, 19.25) -> (-9.075, -19.25)
  line L7 (6.575, -19.25) -> (9.075, -19.25)
  line L8 (6.575, 11.2) -> (6.575, -19.25)
  line L9 (9.075, 11.2) -> (6.575, 11.2)
  line L10 (9.075, -19.25) -> (9.075, 11.2)
  line L11 (0, -19.25) -> (0, 19.25)
  line L12 (-6.575, -19.25) -> (-9.075, -19.25)
  line L13 (-9.075, 11.2) -> (-6.575, 11.2)
  line L14 (-9.075, -19.25) -> (-9.075, 11.2)
  line L15 (-6.575, 11.2) -> (-6.575, -19.25)
  line L16 (-8, 39.25) -> (8, 39.25)
  line L17 (-8, 12.25) -> (-8, 39.25)
  line L18 (8, 12.25) -> (-8, 12.25)
  line L19 (8, 39.25) -> (8, 12.25)
  line L20 (-8, 12.25) -> (8, 39.25)
  line L21 (8, 12.25) -> (-8, 39.25)
  point P6 (0, 0)
  point P1 (0, 0)
  point P10 (0, 19.25)
  point P11 (0, -19.25)
  point P2 (9.075, -19.25)
  point P12 (-9.075, -19.25)
  point P7 (6.575, -19.25)
  point P13 (-6.575, -19.25)
  point P8 (6.575, 11.2)
  point P14 (-6.575, 11.2)
  point P9 (9.075, 11.2)
  point P15 (-9.075, 11.2)
  point P20 (0, 25.75)
  point P4 (-9.075, 19.25)
  point P5 (9.075, 19.25)
  point P16 (8, 39.25)
  point P19 (8, 12.25)
  point P17 (-8, 39.25)
  horizontal L1
  perpendicular L1 L2
  parallel L1 L3
  parallel L2 L4
  coincident L5 P6
  coincident L6 P6
  coincident P1 P6
  horizontal L7
  vertical L8
  horizontal L9
  vertical L10
  midpoint L3 P10
  midpoint L1 P11
  symmetric P2 L11 P12
  symmetric P7 L11 P13
  symmetric P8 L11 P14
  symmetric P9 L11 P15
  horizontal L16
  perpendicular L16 L17
  parallel L16 L18
  parallel L17 L19
  coincident L20 P20
  coincident L21 P20
  coincident L11 P20
  dimension "d1" distance P4 P5 = 18.15
  dimension "d2" distance P2 P5 = 38.5
  dimension "d3" distance P7 P8 = 30.45
  dimension "d4" distance L4 L8 = 2.5
  dimension "d5" distance L3 L18 = 7
  dimension "d6" distance P16 P19 = 27
  dimension "d7" distance P16 P17 = 16
extrude "Extrude1" new body sketch "Sketch1" profile of L1 L2 L3 L4 L7 L8 L9 L10 L12 L13 L14 L15 L17 L18 L19 along normal blind 3
extrude "Extrude2" sketch "Sketch1" profile of L3 L16 L17 L18 L19 blind 7
extrude "Extrude3" new body sketch "Sketch1" profile of L1 L2 L4 L7 L8 L9 L10 L12 L13 L14 L15 against normal blind 11

design "Teensy 4.1"
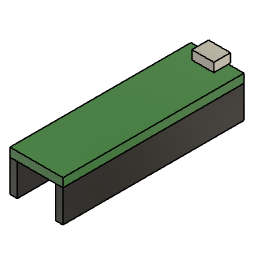
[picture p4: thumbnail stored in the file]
